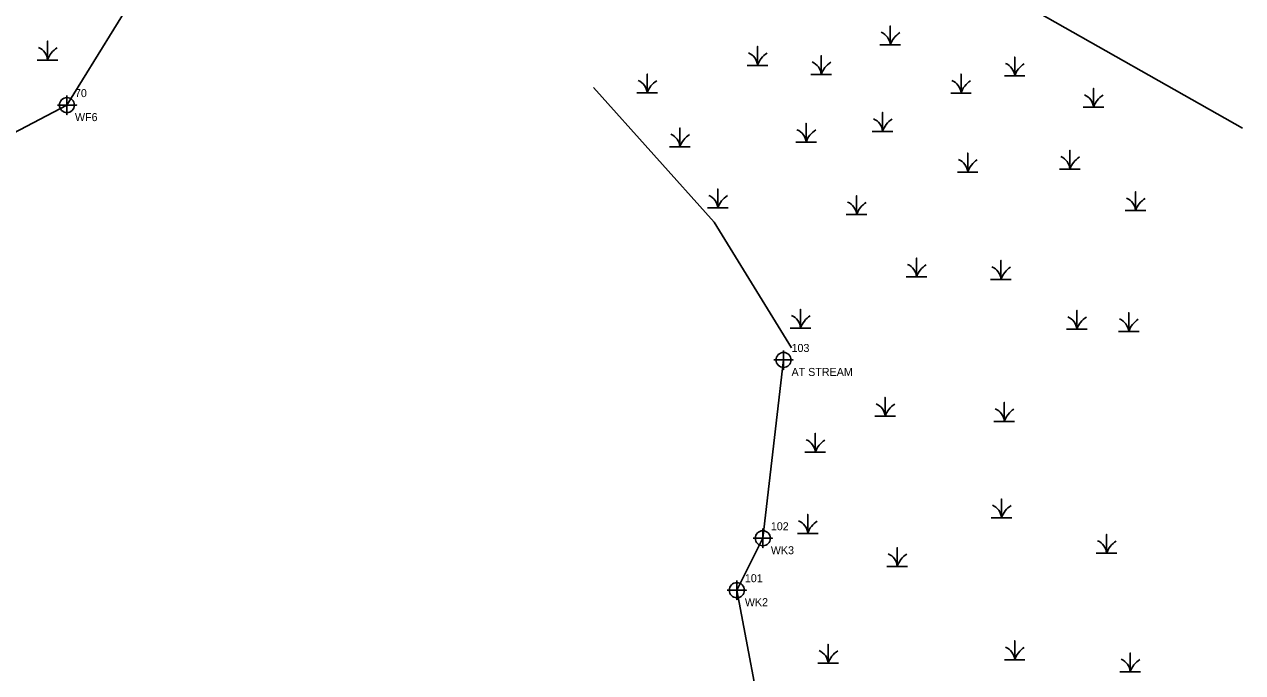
# Model space of a CAD drawing. Extents: x 2189822 to 2190837, y 387253 to 388663.
# Drawn here: x 2190174.5 to 2190555.2, y 387688.6 to 387891.4 of the extents above; entities that cross this region are included whole.
import ezdxf

# ---------------------------------------------------------------- set-up
doc = ezdxf.new("R2010")
doc.units = 0
for name, color, linetype in [('COGO Default Chain', 7, 'Continuous'), ('DTM Contours Major', 7, 'Continuous'), ('DTM Contours Minor', 7, 'Continuous'), ('Exist DTM Breakline Cogo Elevation', 7, 'Continuous'), ('Exist DTM Breakline Cogo Number', 7, 'Continuous')]:
    doc.layers.add(name, color=color, linetype=linetype)

msp = doc.modelspace()

# ---------------------------------------------------------------- linework, layer by layer
at = {"layer": 'DTM Contours Major'}
for points in [[(2190187.82, 387869.13), (2190187.82, 387863.13), (2190187.82, 387866.13), (2190190.82, 387866.13), (2190184.82, 387866.13)], [(2190411.74, 387789.43), (2190411.74, 387783.43), (2190411.74, 387786.43), (2190414.74, 387786.43), (2190408.74, 387786.43)], [(2190405.27, 387733.67), (2190405.27, 387727.67), (2190405.27, 387730.67), (2190408.27, 387730.67), (2190402.27, 387730.67)], [(2190397.15, 387717.42), (2190397.15, 387711.42), (2190397.15, 387714.42), (2190400.15, 387714.42), (2190394.15, 387714.42)]]:
    msp.add_lwpolyline(points, dxfattribs=at)
for centre in [(2190187.82, 387866.13), (2190411.74, 387786.43), (2190405.27, 387730.67), (2190397.15, 387714.42)]:
    msp.add_circle(centre, 2.34, dxfattribs=at)
at = {"layer": 'Exist DTM Breakline Cogo Elevation'}
for p, q in [((2190445.1, 387887.65), (2190445.1, 387887.65)), ((2190181.76, 387882.91), (2190181.76, 387882.91)), ((2190403.61, 387881.24), (2190403.61, 387881.24)), ((2190423.51, 387878.36), (2190423.51, 387878.36)), ((2190483.97, 387877.93), (2190483.97, 387877.93)), ((2190369.13, 387872.61), (2190369.13, 387872.61)), ((2190467.2, 387872.59), (2190467.2, 387872.59)), ((2190508.6, 387868.11), (2190508.6, 387868.11)), ((2190442.67, 387860.59), (2190442.67, 387860.59)), ((2190379.37, 387855.75), (2190379.37, 387855.75)), ((2190418.77, 387857.2), (2190418.77, 387857.2)), ((2190469.28, 387847.86), (2190469.28, 387847.86)), ((2190501.24, 387848.76), (2190501.24, 387848.76)), ((2190391.2, 387836.66), (2190391.2, 387836.66)), ((2190434.58, 387834.56), (2190434.58, 387834.56)), ((2190521.75, 387835.8), (2190521.75, 387835.8)), ((2190453.32, 387815.06), (2190453.32, 387815.06)), ((2190479.68, 387814.3), (2190479.68, 387814.3)), ((2190417.06, 387799.06), (2190417.06, 387799.06)), ((2190503.39, 387798.68), (2190503.39, 387798.68)), ((2190519.59, 387797.99), (2190519.59, 387797.99)), ((2190443.48, 387771.47), (2190443.48, 387771.47)), ((2190480.73, 387769.9), (2190480.73, 387769.9)), ((2190480.73, 387769.9), (2190480.73, 387769.9)), ((2190421.67, 387760.23), (2190421.67, 387760.23)), ((2190479.83, 387739.73), (2190479.83, 387739.73)), ((2190419.29, 387734.88), (2190419.29, 387734.88)), ((2190512.7, 387728.64), (2190512.7, 387728.64)), ((2190447.26, 387724.52), (2190447.26, 387724.52)), ((2190425.67, 387694.28), (2190425.67, 387694.28)), ((2190483.97, 387695.36), (2190483.97, 387695.36)), ((2190520.08, 387691.57), (2190520.08, 387691.57))]:
    msp.add_line(p, q, dxfattribs=at)
for points in [[(2190441.87, 387884.98), (2190445.1, 387884.98), (2190445.1, 387890.89), (2190445.1, 387884.98), (2190448.33, 387884.98)], [(2190178.53, 387880.23), (2190181.76, 387880.23), (2190181.76, 387886.15), (2190181.76, 387880.23), (2190184.99, 387880.23)], [(2190400.38, 387878.57), (2190403.61, 387878.57), (2190403.61, 387884.49), (2190403.61, 387878.57), (2190406.83, 387878.57)], [(2190420.28, 387875.69), (2190423.51, 387875.69), (2190423.51, 387881.61), (2190423.51, 387875.69), (2190426.74, 387875.69)], [(2190480.74, 387875.25), (2190483.97, 387875.25), (2190483.97, 387881.17), (2190483.97, 387875.25), (2190487.19, 387875.25)], [(2190365.9, 387869.94), (2190369.13, 387869.94), (2190369.13, 387875.86), (2190369.13, 387869.94), (2190372.35, 387869.94)], [(2190463.97, 387869.91), (2190467.2, 387869.91), (2190467.2, 387875.83), (2190467.2, 387869.91), (2190470.42, 387869.91)], [(2190505.37, 387865.44), (2190508.6, 387865.44), (2190508.6, 387871.36), (2190508.6, 387865.44), (2190511.82, 387865.44)], [(2190439.45, 387857.92), (2190442.68, 387857.92), (2190442.68, 387863.84), (2190442.68, 387857.92), (2190445.9, 387857.92)], [(2190376.15, 387853.08), (2190379.37, 387853.08), (2190379.37, 387859), (2190379.37, 387853.08), (2190382.6, 387853.08)], [(2190415.55, 387854.52), (2190418.77, 387854.52), (2190418.77, 387860.44), (2190418.77, 387854.52), (2190422, 387854.52)], [(2190466.05, 387845.19), (2190469.28, 387845.19), (2190469.28, 387851.11), (2190469.28, 387845.19), (2190472.5, 387845.19)], [(2190498.01, 387846.09), (2190501.24, 387846.09), (2190501.24, 387852), (2190501.24, 387846.09), (2190504.47, 387846.09)], [(2190387.97, 387833.98), (2190391.2, 387833.98), (2190391.2, 387839.9), (2190391.2, 387833.98), (2190394.42, 387833.98)], [(2190518.53, 387833.12), (2190521.75, 387833.12), (2190521.75, 387839.04), (2190521.75, 387833.12), (2190524.98, 387833.12)], [(2190431.35, 387831.88), (2190434.58, 387831.88), (2190434.58, 387837.8), (2190434.58, 387831.88), (2190437.81, 387831.88)], [(2190450.1, 387812.39), (2190453.32, 387812.39), (2190453.32, 387818.31), (2190453.32, 387812.39), (2190456.55, 387812.39)], [(2190476.46, 387811.63), (2190479.69, 387811.63), (2190479.69, 387817.55), (2190479.69, 387811.63), (2190482.91, 387811.63)], [(2190413.84, 387796.39), (2190417.07, 387796.39), (2190417.07, 387802.31), (2190417.07, 387796.39), (2190420.29, 387796.39)], [(2190500.17, 387796.01), (2190503.39, 387796.01), (2190503.39, 387801.93), (2190503.39, 387796.01), (2190506.62, 387796.01)], [(2190516.37, 387795.31), (2190519.59, 387795.31), (2190519.59, 387801.23), (2190519.59, 387795.31), (2190522.82, 387795.31)], [(2190440.25, 387768.8), (2190443.48, 387768.8), (2190443.48, 387774.72), (2190443.48, 387768.8), (2190446.7, 387768.8)], [(2190477.5, 387767.22), (2190480.73, 387767.22), (2190480.73, 387773.14), (2190480.73, 387767.22), (2190483.95, 387767.22)], [(2190477.5, 387767.22), (2190480.73, 387767.22), (2190480.73, 387773.14), (2190480.73, 387767.22), (2190483.95, 387767.22)], [(2190418.44, 387757.56), (2190421.67, 387757.56), (2190421.67, 387763.48), (2190421.67, 387757.56), (2190424.89, 387757.56)], [(2190476.6, 387737.06), (2190479.83, 387737.06), (2190479.83, 387742.98), (2190479.83, 387737.06), (2190483.05, 387737.06)], [(2190416.07, 387732.2), (2190419.29, 387732.2), (2190419.29, 387738.12), (2190419.29, 387732.2), (2190422.52, 387732.2)], [(2190509.48, 387725.97), (2190512.7, 387725.97), (2190512.7, 387731.88), (2190512.7, 387725.97), (2190515.93, 387725.97)], [(2190444.03, 387721.85), (2190447.26, 387721.85), (2190447.26, 387727.77), (2190447.26, 387721.85), (2190450.48, 387721.85)], [(2190422.44, 387691.6), (2190425.67, 387691.6), (2190425.67, 387697.52), (2190425.67, 387691.6), (2190428.89, 387691.6)], [(2190480.74, 387692.68), (2190483.97, 387692.68), (2190483.97, 387698.6), (2190483.97, 387692.68), (2190487.19, 387692.68)], [(2190516.85, 387688.89), (2190520.08, 387688.89), (2190520.08, 387694.81), (2190520.08, 387688.89), (2190523.3, 387688.89)]]:
    msp.add_lwpolyline(points, dxfattribs=at)
for centre, radius, start, end in [((2190440.5, 387884.64), 4.61, 4.1403, 67.535), ((2190451.94, 387882.7), 7.21, 122.1274, 161.6222), ((2190177.16, 387879.9), 4.61, 4.1403, 67.535), ((2190188.6, 387877.96), 7.21, 122.1274, 161.6222), ((2190399.01, 387878.24), 4.61, 4.1403, 67.535), ((2190410.45, 387876.3), 7.21, 122.1274, 161.6222), ((2190418.91, 387875.36), 4.61, 4.1403, 67.535), ((2190430.35, 387873.42), 7.21, 122.1274, 161.6222), ((2190479.37, 387874.92), 4.61, 4.1403, 67.535), ((2190490.81, 387872.98), 7.21, 122.1274, 161.6222), ((2190364.53, 387869.61), 4.61, 4.1403, 67.535), ((2190375.97, 387867.67), 7.21, 122.1274, 161.6222), ((2190462.6, 387869.58), 4.61, 4.1403, 67.535), ((2190474.04, 387867.64), 7.21, 122.1274, 161.6222), ((2190504, 387865.11), 4.61, 4.1403, 67.535), ((2190515.44, 387863.17), 7.21, 122.1274, 161.6222), ((2190438.08, 387857.58), 4.61, 4.1403, 67.535), ((2190449.52, 387855.64), 7.21, 122.1274, 161.6222), ((2190414.18, 387854.19), 4.61, 4.1403, 67.535), ((2190425.62, 387852.25), 7.21, 122.1274, 161.6222), ((2190374.77, 387852.75), 4.61, 4.1403, 67.535), ((2190386.21, 387850.81), 7.21, 122.1274, 161.6222), ((2190496.64, 387845.75), 4.61, 4.1403, 67.535), ((2190508.08, 387843.81), 7.21, 122.1274, 161.6222), ((2190464.68, 387844.86), 4.61, 4.1403, 67.535), ((2190476.12, 387842.92), 7.21, 122.1274, 161.6222), ((2190386.6, 387833.65), 4.61, 4.1403, 67.535), ((2190398.04, 387831.71), 7.21, 122.1274, 161.6222), ((2190429.98, 387831.55), 4.61, 4.1403, 67.535), ((2190441.42, 387829.61), 7.21, 122.1274, 161.6222), ((2190517.15, 387832.79), 4.61, 4.1403, 67.535), ((2190528.59, 387830.85), 7.21, 122.1274, 161.6222), ((2190448.72, 387812.06), 4.61, 4.1403, 67.535), ((2190460.16, 387810.12), 7.21, 122.1274, 161.6222), ((2190475.09, 387811.3), 4.61, 4.1403, 67.535), ((2190486.53, 387809.36), 7.21, 122.1274, 161.6222), ((2190412.47, 387796.06), 4.61, 4.1403, 67.535), ((2190423.91, 387794.12), 7.21, 122.1274, 161.6222), ((2190498.79, 387795.68), 4.61, 4.1403, 67.535), ((2190510.24, 387793.74), 7.21, 122.1274, 161.6222), ((2190514.99, 387794.98), 4.61, 4.1403, 67.535), ((2190526.43, 387793.04), 7.21, 122.1274, 161.6222), ((2190438.88, 387768.47), 4.61, 4.1403, 67.535), ((2190450.32, 387766.53), 7.21, 122.1274, 161.6222), ((2190476.13, 387766.89), 4.61, 4.1403, 67.535), ((2190476.13, 387766.89), 4.61, 4.1403, 67.535), ((2190487.57, 387764.95), 7.21, 122.1274, 161.6222), ((2190487.57, 387764.95), 7.21, 122.1274, 161.6222), ((2190417.07, 387757.22), 4.61, 4.1403, 67.535), ((2190428.51, 387755.28), 7.21, 122.1274, 161.6222), ((2190475.23, 387736.73), 4.61, 4.1403, 67.535), ((2190486.67, 387734.79), 7.21, 122.1274, 161.6222), ((2190414.69, 387731.87), 4.61, 4.1403, 67.535), ((2190426.13, 387729.93), 7.21, 122.1274, 161.6222), ((2190508.1, 387725.63), 4.61, 4.1403, 67.535), ((2190519.54, 387723.69), 7.21, 122.1274, 161.6222), ((2190442.66, 387721.52), 4.61, 4.1403, 67.535), ((2190454.1, 387719.58), 7.21, 122.1274, 161.6222), ((2190421.07, 387691.27), 4.61, 4.1403, 67.535), ((2190432.51, 387689.33), 7.21, 122.1274, 161.6222), ((2190479.37, 387692.35), 4.61, 4.1403, 67.535), ((2190490.81, 387690.41), 7.21, 122.1274, 161.6222), ((2190515.48, 387688.56), 4.61, 4.1403, 67.535), ((2190526.92, 387686.62), 7.21, 122.1274, 161.6222)]:
    msp.add_arc(centre, radius, start, end, dxfattribs=at)
at = {"layer": 'Exist DTM Breakline Cogo Number'}
for p, q in [((2190486.31, 387897.92), (2190555.2, 387858.91)), ((2190352.33, 387871.62), (2190390.04, 387829.56)), ((2190414.24, 387790.18), (2190390.04, 387829.56))]:
    msp.add_line(p, q, dxfattribs=at)
for points in [[(2190311.6, 387912.32), (2190282.87, 387902.15), (2190276.9, 387926.61), (2190246.66, 387930.44), (2190212.31, 387905.81), (2190187.82, 387866.13), (2190141.4, 387841.78), (2190098.41, 387819.25)], [(2190405.27, 387730.67), (2190411.74, 387786.43)], [(2190346.43, 387552.46), (2190289.14, 387589.41), (2190330.02, 387625.97), (2190346.89, 387660.22), (2190381.54, 387653.46), (2190395.53, 387607.4), (2190415.3, 387618.48), (2190397.15, 387714.42), (2190405.27, 387730.67)]]:
    msp.add_lwpolyline(points, dxfattribs=at)

# ---------------------------------------------------------------- texts
at = {"layer": 'COGO Default Chain'}
for s, p in [('WF6', (2190190.32, 387861.13)), ('AT STREAM', (2190414.24, 387781.43)), ('WK3', (2190407.77, 387725.67)), ('WK2', (2190399.65, 387709.42))]:
    msp.add_text(s, height=2.5, dxfattribs=at).set_placement(p)
at = {"layer": 'DTM Contours Minor'}
for s, p in [('70', (2190190.32, 387868.63)), ('103', (2190414.24, 387788.93)), ('102', (2190407.77, 387733.17)), ('101', (2190399.65, 387716.92))]:
    msp.add_text(s, height=2.5, dxfattribs=at).set_placement(p)

doc.saveas('drawing.dxf')
